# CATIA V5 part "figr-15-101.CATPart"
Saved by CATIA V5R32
Part number: Part1
Bounding box of the stored display mesh (mm): x -52.43 to 60.529, y -25.631 to 32.893, z 0 to 4
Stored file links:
  D:\PROJECTS\Project 2022\CATIA V5 6R 2022\Resources\Part Files\c15_catia_v5_6r2022_prt\figr-15-101.CATPart
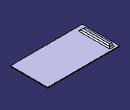
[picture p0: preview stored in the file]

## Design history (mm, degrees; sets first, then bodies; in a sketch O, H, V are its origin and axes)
SheetMetalParameters1: Thickness 1, BendRadius 5, KFactor 0.5 {= log(min(100,max(20*SheetMetalParameters1.BendRadius,SheetMetalParameters1.Thickness)/SheetMetalParameters1.Thickness))/log(100)/2}, ReliefRadialLength 1, ReliefAxialLength 2, MinimumBendRadius 0
Body1 (main body)
  Sketch1 on xy-plane, origin (0, 0, 0), H (1, 0, 0), V (0, 1, 0)
    line L1 (-52.4297, 32.8934) -> (60.5286, 32.8934)
    line L2 (60.5286, 32.8934) -> (60.5286, -25.6312)
    line L3 (60.5286, -25.6312) -> (-52.4297, -25.6312)
    line L4 (-52.4297, -25.6312) -> (-52.4297, 32.8934)
    horizontal: L1 H, L3 H
    vertical: L2 V, L4 V
  Wall1: Thickness 1, Profile Sketch1
  Sketch2 on face of Wall1, origin (0, 0, 1), H (1, 0, 0), V (0, 1, 0)
    line L1 (-47.3159, -16.5837) -> (-43.073, -16.5837)
    line L2 (-43.073, -16.5837) -> (-43.073, 26.788)
    line L3 (-43.073, 26.788) -> (-47.3159, 26.788)
    line L4 (-47.3159, 26.788) -> (-47.3159, -16.5837)
    horizontal: L1 H, L3 H
    vertical: L2 V, L4 V
  d_Stamp1: Stamp_FilletRadius 2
